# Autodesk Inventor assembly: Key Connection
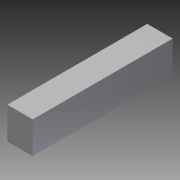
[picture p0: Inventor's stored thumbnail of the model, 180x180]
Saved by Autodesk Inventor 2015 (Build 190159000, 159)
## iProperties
Created: 2007-02
Part Number: Key Connection
Document SubType Name: Assembly
Designer: Autodesk, Inc.
Mass: 13.8362 g
Surface Area: 10.9879 cm^2
Volume: 1.76033 cm^3
Density: 7.86 g/cm^3
ClientObjectVersion: 1
Author: Autodesk, Inc.
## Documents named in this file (2)
- C:\Users\Public\Documents\Autodesk\Inventor 2015\Samples\Models\Assemblies\Blower\Blower\Design Accelerator\Key Connection1.iam
- C:\Users\Public\Documents\Autodesk\Inventor 2015\Samples\Standard Parts\en-US\USAS B17.1(1)\USAS B17.1 - 5_16 x 1_4 x 1 3_8.ipt
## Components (1 placed, 1 different names)
1. Rectangular 5/16 x 1/4 x 1 3/8:1
